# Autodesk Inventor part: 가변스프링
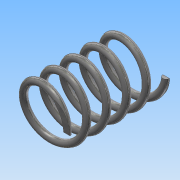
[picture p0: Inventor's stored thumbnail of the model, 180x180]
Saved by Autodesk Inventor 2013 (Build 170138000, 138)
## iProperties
Created: 2018-10
Part Number: 가변스프링
Material: 스테인리스강
Document SubType Name: Modeling
Designer: Administrator
Density: 8.08 g/cm^3
Mass: 6.29295 g
Surface Area: 15.7914 cm^2
Volume: 0.778831 cm^3
Author: Administrator
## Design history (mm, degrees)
sketch "스케치1"
  geometry: L1 (0, 0)-(0, -30.063); L2 (0, 0)-(8, 0); L3 (0, -30.063)-(8, -30.063); C1 r 1 at (8, 0); 1 further point
  constraints: 6 end point, 2 coincident, 1 centre point, 1 parallel, 1 perpendicular, 1 vertical
  dimensions: "d0" = 30.06326 distance of L1.start L1.end (derived); "d2" = 8 distance of L1.start L2.end; "d3" = 2 diameter of C1
feature "코일1" sketch "스케치1" pitch "d4" = 10; turns "d6" = 5; dims "d5" = 30.06326 (= d0), "d7" = 0, angle "d8" = 90 deg, angle "d9" = 90 deg, "d10" = 0, "d11" = 0
sketch "스케치2"
  geometry: L1 (-30.063, 10)-(0, 10); L2 (0, 10)-(0, -10); L3 (0, -10)-(-30.063, -10); L4 (-30.063, -10)-(-30.063, 10); 2 further points
  constraints: 8 end point, 2 parallel, 1 coincident, 1 horizontal, 1 midpoint, 1 perpendicular
  dimensions: "d12" = 20 distance of L1.end L2.end; "d15" = 30.06326 distance of L2.end L3.end (derived)
extrude "돌출1" sketch "스케치2" stored distance "d16" = 0; taper "d17" = 0 deg
node "솔리드1"
